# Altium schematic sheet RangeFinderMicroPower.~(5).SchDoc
size A; DocumentNumber: 3; SheetNumber: 3; SheetTotal: 6
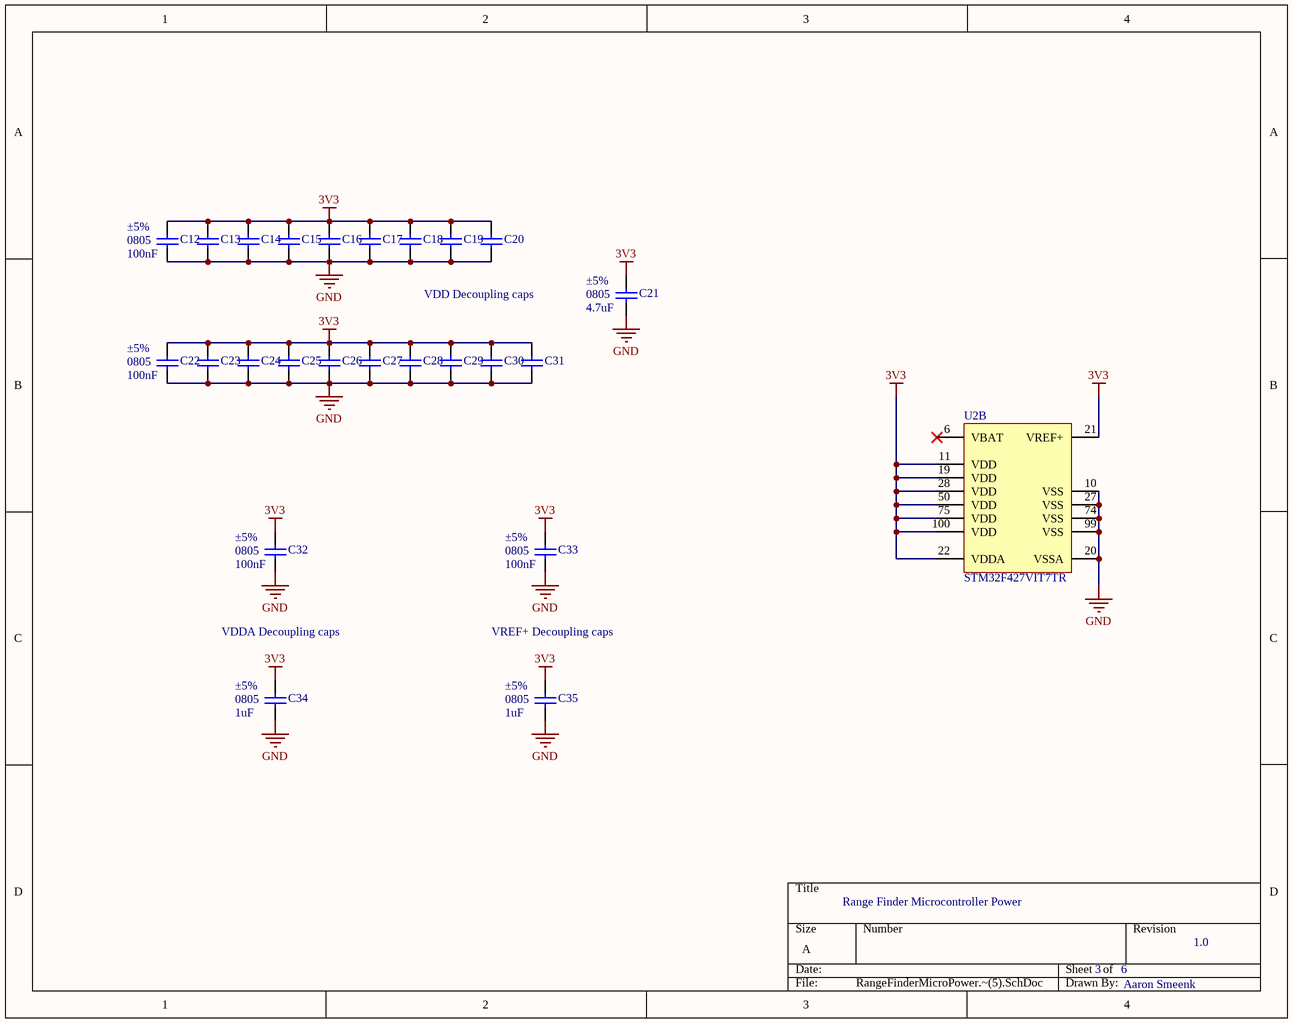
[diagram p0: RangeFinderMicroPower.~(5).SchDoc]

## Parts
C12  value 100nF  Tolerance: ±5%  Case-EIA: 0805  [CAPC0805(2012)100_L]  (hidden comment: CAP 100nF 6.3V 0805(2012))
C13  CAP 100nF 6.3V 0805(2012)  [CAPC0805(2012)100_L]  (value not drawn)
C14  CAP 100nF 6.3V 0805(2012)  [CAPC0805(2012)100_L]  (value not drawn)
C15  CAP 100nF 6.3V 0805(2012)  [CAPC0805(2012)100_L]  (value not drawn)
C16  CAP 100nF 6.3V 0805(2012)  [CAPC0805(2012)100_L]  (value not drawn)
C17  CAP 100nF 6.3V 0805(2012)  [CAPC0805(2012)100_L]  (value not drawn)
C18  CAP 100nF 6.3V 0805(2012)  [CAPC0805(2012)100_L]  (value not drawn)
C19  CAP 100nF 6.3V 0805(2012)  [CAPC0805(2012)100_L]  (value not drawn)
C20  CAP 100nF 6.3V 0805(2012)  [CAPC0805(2012)100_L]  (value not drawn)
C21  value 4.7uF  Case-EIA: 0805  Tolerance: ±5%  [CAPC0805(2012)145_N]  (hidden comment: CAP 4.7uF 6.3V 0805(2012))
C22  value 100nF  Tolerance: ±5%  Case-EIA: 0805  [CAPC0805(2012)100_L]  (hidden comment: CAP 100nF 6.3V 0805(2012))
C23  CAP 100nF 6.3V 0805(2012)  [CAPC0805(2012)100_L]  (value not drawn)
C24  CAP 100nF 6.3V 0805(2012)  [CAPC0805(2012)100_L]  (value not drawn)
C25  CAP 100nF 6.3V 0805(2012)  [CAPC0805(2012)100_L]  (value not drawn)
C26  CAP 100nF 6.3V 0805(2012)  [CAPC0805(2012)100_L]  (value not drawn)
C27  CAP 100nF 6.3V 0805(2012)  [CAPC0805(2012)100_L]  (value not drawn)
C28  CAP 100nF 6.3V 0805(2012)  [CAPC0805(2012)100_L]  (value not drawn)
C29  CAP 100nF 6.3V 0805(2012)  [CAPC0805(2012)100_L]  (value not drawn)
C30  CAP 100nF 6.3V 0805(2012)  [CAPC0805(2012)100_L]  (value not drawn)
C31  CAP 100nF 6.3V 0805(2012)  [CAPC0805(2012)100_L]  (value not drawn)
C32  value 100nF  Tolerance: ±5%  Case-EIA: 0805  [CAPC0805(2012)100_L]  (hidden comment: CAP 100nF 6.3V 0805(2012))
C33  value 100nF  Tolerance: ±5%  Case-EIA: 0805  [CAPC0805(2012)100_L]  (hidden comment: CAP 100nF 6.3V 0805(2012))
C34  value 1uF  Case-EIA: 0805  Tolerance: ±5%  [CAPC0805(2012)145_N]  (hidden comment: CAP 1uF 6.3V 0805(2012))
C35  value 1uF  Case-EIA: 0805  Tolerance: ±5%  [CAPC0805(2012)145_N]  (hidden comment: CAP 1uF 6.3V 0805(2012))
U2  STM32F427VIT7TR  [STM-LQFP100_N]  (part B of 2)

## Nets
3V3: C12.2 C13.2 C14.2 C15.2 C16.2 C17.2 C18.2 C19.2 C20.2 C21.2 C22.2 C23.2 C24.2 C25.2 C26.2 C27.2 C28.2 C29.2 C30.2 C31.2 C32.2 C33.2 C34.2 C35.2 U2.11(VDD) U2.19(VDD) U2.21(VREF+) U2.22(VDDA) U2.28(VDD) U2.50(VDD) U2.75(VDD) U2.100(VDD)
GND: C12.1 C13.1 C14.1 C15.1 C16.1 C17.1 C18.1 C19.1 C20.1 C21.1 C22.1 C23.1 C24.1 C25.1 C26.1 C27.1 C28.1 C29.1 C30.1 C31.1 C32.1 C33.1 C34.1 C35.1 U2.10(VSS) U2.20(VSSA) U2.27(VSS) U2.74(VSS) U2.99(VSS)

Not connected (* = marked no-connect by the designer): U2 6(VBAT)*

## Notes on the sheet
- VDD Decoupling caps
- VDDA Decoupling caps
- VREF+ Decoupling caps
- Range Finder Microcontroller Power
- 3
- 6
- 1.0
- Aaron Smeenk

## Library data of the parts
C12 C22 C32 C33 = CMP-1036-04390-1: CAP 100nF 6.3V ±5% 0805 (2012 Metric) Thickness 1mm SMD; Case-Metric: 2012
C13-C20 C23-C31 = CMP-1036-04390-1: CAP 100nF 6.3V ±5% 0805 (2012 Metric) Thickness 1mm SMD; Case-Metric: 2012; Case-EIA: 0805
C21 = CMP-1036-04781-1: CAP 4.7uF 6.3V ±5% 0805 (2012 Metric) Thickness 1.45mm SMD; Case-Metric: 2012
C34 C35 = CMP-1036-04781-1: CAP 1uF 6.3V ±5% 0805 (2012 Metric) Thickness 1.45mm SMD; Case-Metric: 2012
U2 = CMP-0243-00026-2: ARM Cortex-M4 32-bit MCU+FPU, 210 DMIPS, 2048 kB Flash, 256 kB Internal RAM, 82 I/Os, 100-pin LQFP, -40 to 105 degC, Tape and Reel; Manufacturer: STMicroelectronics; Supply Voltage(Vcc) max (V): 3.6; Supply Voltage(Vcc) min (V): 1.8; FLASH Size (Prog) (kB): 2048; Operating Frequency(F) (Processor speed) (MHz): 168; D/A Converter: 2x12-bit; Internal RAM Size (kB): 256; I/Os (High Current): 82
